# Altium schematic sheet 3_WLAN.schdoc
size 302 x 215 mm; Symbol: Sheet_A4; Device: Sheet_A4; @Project Name: Yuzukilizard; REV: 1.0; Date: 2022-10-08; Sheet: 1/1; Draw By: GloomyGhost; Company: YuzukiHD
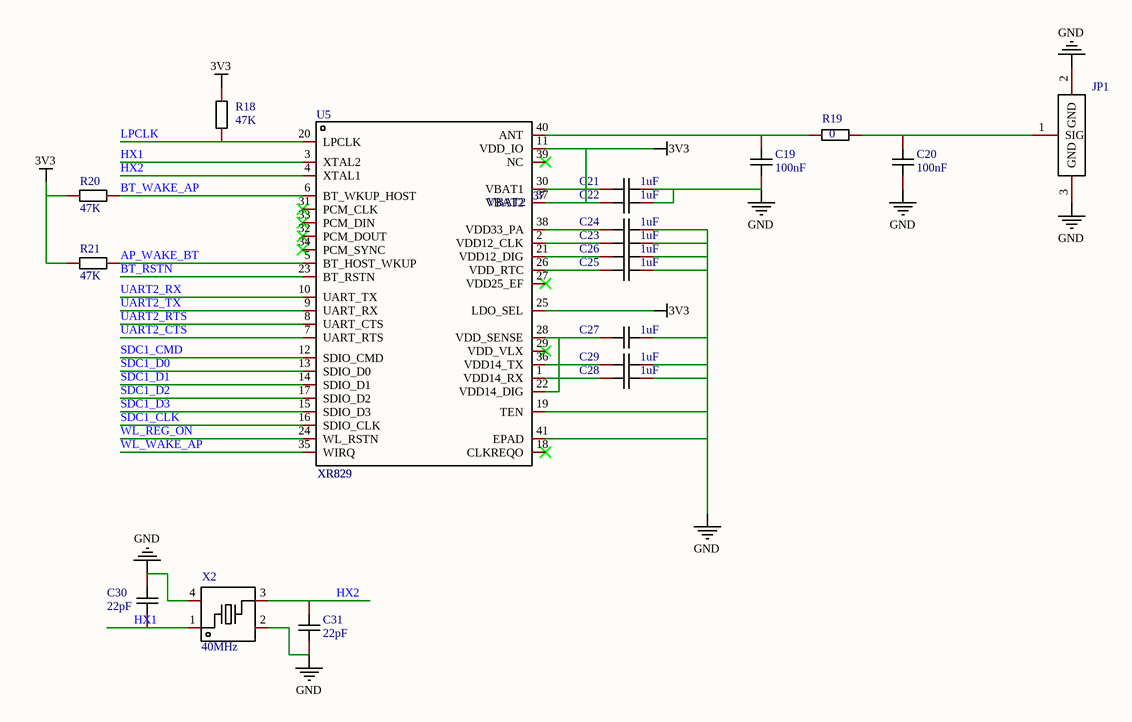
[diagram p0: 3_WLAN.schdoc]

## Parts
C19  value 100nF  [C0402]  (hidden comment: CAP_0402)
C20  value 100nF  [C0402]  (hidden comment: CAP_0402)
C21  value 1uF  [C0402]  (hidden comment: CAP_0402)
C22  value 1uF  [C0402]  (hidden comment: CAP_0402)
C23  value 1uF  [C0402]  (hidden comment: CAP_0402)
C24  value 1uF  [C0402]  (hidden comment: CAP_0402)
C25  value 1uF  [C0402]  (hidden comment: CAP_0402)
C26  value 1uF  [C0402]  (hidden comment: CAP_0402)
C27  value 1uF  [C0402]  (hidden comment: CAP_0402)
C28  value 1uF  [C0402]  (hidden comment: CAP_0402)
C29  value 1uF  [C0402]  (hidden comment: CAP_0402)
C30  value 22pF  [C0402]  (hidden comment: CAP_0402)
C31  value 22pF  [C0402]  (hidden comment: CAP_0402)
JP1  U.FL-R-SMT-1(80)  [RF-SMD_FRF05002-JSS103M]  (value not drawn)
R18  value 47K  [R0402]  (hidden comment: Res_0402)
R19  value 0  [R0402]  (hidden comment: Res_0402)
R20  value 47K  [R0402]  (hidden comment: Res_0402)
R21  value 47K  [R0402]  (hidden comment: Res_0402)
U5  XR829  NAME: VBAT2  NUMBER: 37  [QFN-40_L5.0-W5.0-P0.40-BL-EP3.4]
X2  value 40MHz  [CRYSTAL-SMD_4P-L2.0-W1.6-BL]  (hidden comment: 7D040000I01)

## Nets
3V3: C21.1 C22.1 R18.2 R20.2 R21.2 U5.11(VDD_IO) U5.25(LDO_SEL) U5.30(VBAT1) U5.37(VBAT2)
GND: C19.1 C20.1 C21.2 C22.2 C23.2 C24.2 C25.2 C26.2 C27.2 C28.2 C29.2 C30.2 C31.2 JP1.2(GND) JP1.3(GND) U5.19(TEN) U5.41(EPAD) X2.2(GND) X2.4(GND)
AP_WAKE_BT: R21.1 U5.5(BT_HOST_WKUP)
BT_RSTN: U5.23(BT_RSTN)
BT_WAKE_AP: R20.1 U5.6(BT_WKUP_HOST)
HX1: C30.1 U5.3(XTAL2) X2.1
HX2: C31.1 U5.4(XTAL1) X2.3
LPCLK: R18.1 U5.20(LPCLK)
SDC1_CLK: U5.16(SDIO_CLK)
SDC1_CMD: U5.12(SDIO_CMD)
SDC1_D0: U5.13(SDIO_D0)
SDC1_D1: U5.14(SDIO_D1)
SDC1_D2: U5.17(SDIO_D2)
SDC1_D3: U5.15(SDIO_D3)
UART2_CTS: U5.7(UART_RTS)
UART2_RTS: U5.8(UART_CTS)
UART2_RX: U5.10(UART_TX)
UART2_TX: U5.9(UART_RX)
WL_REG_ON: U5.24(WL_RSTN)
WL_WAKE_AP: U5.35(WIRQ)
NetC19_2: C19.2 R19.1 U5.40(ANT)
NetC20_2: C20.2 JP1.1(SIG) R19.2
NetC23_1: C23.1 U5.2(VDD12_CLK)
NetC24_1: C24.1 U5.38(VDD33_PA)
NetC25_1: C25.1 U5.26(VDD_RTC)
NetC26_1: C26.1 U5.21(VDD12_DIG)
NetC27_1: C27.1 C28.1 C29.1 U5.1(VDD14_RX) U5.22(VDD14_DIG) U5.28(VDD_SENSE) U5.36(VDD14_TX)

Not connected (* = marked no-connect by the designer): U5 18(CLKREQO)* 27(VDD25_EF)* 29(VDD_VLX)* 31(PCM_CLK)* 32(PCM_DOUT)* 33(PCM_DIN)* 34(PCM_SYNC)* 39(NC)*

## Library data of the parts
C19-C31 = CAP_0402: 容值:100nF;精度:±10%;额定电压:16V;温度系数:X7R;; Symbol: C1210X7R475K630NT; Convert to PCB: yes
JP1 = U.FL-R-SMT-1(80): 连接器类型:板端;射频系列:IPEX;接口类型:内针;端口数量:1;阻抗:50;频率-最大值:6GHz;样式:-;接口直径:2mm;接口长度/高度:1.25mm;工作温度范围:-40~+90;; Manufacturer: HRS(广濑); Add into BOM: yes; Impedance: 50
R18-R21 = Res_0402: Symbol: 电阻; Convert to PCB: yes
U5 = XR829: Manufacturer: Allwinner; Pin Type: IN; Add into BOM: yes
X2 = 7D040000I01: 频率公差:±10ppm;频率公差:±10ppm;负载电容:10pF;工作温度:-20~+70;工作温度:-20~+70;频率:40MHz;晶振类型:贴片无源晶振;等效串联电阻(ESR):35Ω;; Manufacturer: HD(海德频率); Add into BOM: yes; Frequency Tolerance: ±10ppm; Load Capacitance: 10pF; Crystal Type: 贴片无源晶振; Equivalent Series Resistance (ESR): 35Ω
